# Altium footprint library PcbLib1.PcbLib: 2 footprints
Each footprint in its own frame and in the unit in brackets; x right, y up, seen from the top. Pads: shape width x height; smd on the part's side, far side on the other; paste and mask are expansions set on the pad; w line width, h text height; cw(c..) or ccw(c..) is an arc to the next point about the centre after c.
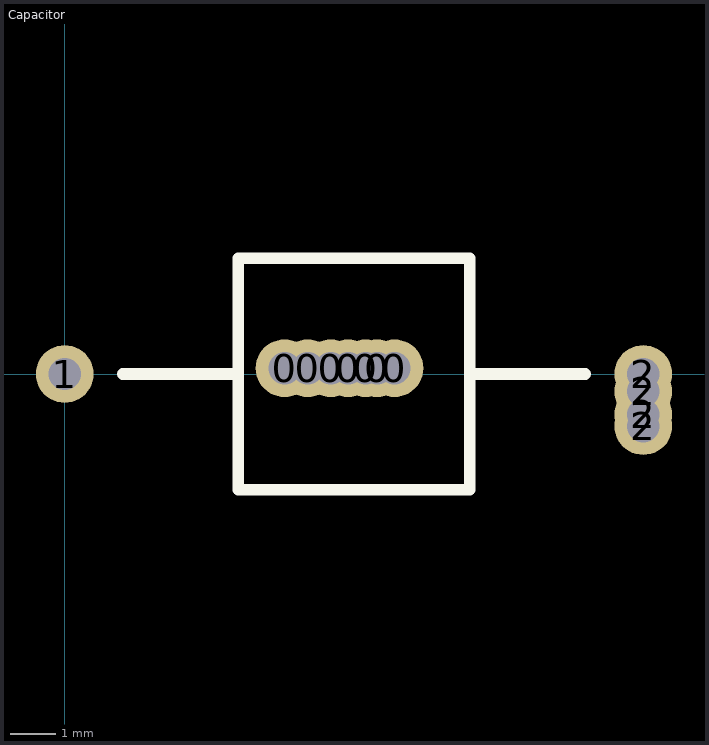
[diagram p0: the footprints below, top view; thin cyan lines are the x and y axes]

## Capacitor [mil]
pads (12):
  round 50 hole 28: 0(190,5) 0(210,5) 0(230,5) 0(245,5) 0(260,5) 0(270,5) 0(285,5) 1(0,0) 2(500,-45) 2(500,-35) 2(500,-15) 2(500,0)
Top Overlay:
  lines w10: 50,0 150,0 ; 350,0 450,0 ; 150,0 150,100 350,100 350,-100 150,-100 150,0

## PCBComponent_1 [mil]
